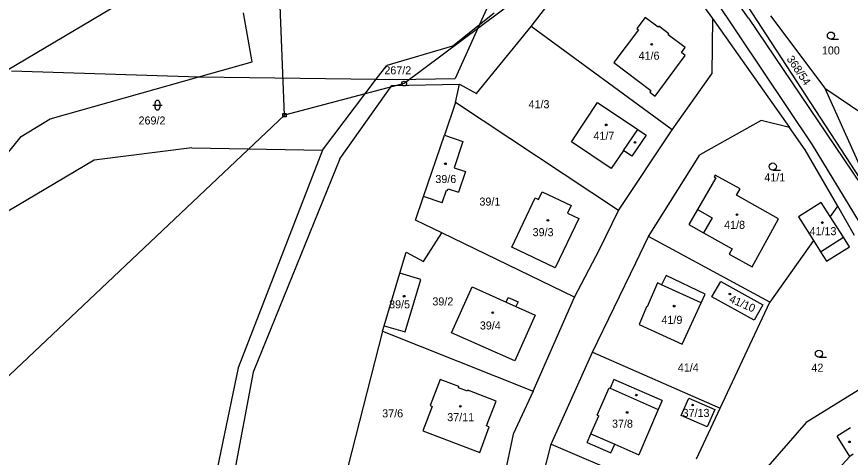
# Model space of a CAD drawing. Extents: x -762263 to -760336, y -1154405 to -1152076.
# Drawn here: x -761872.6 to -761696.3, y -1152343.6 to -1152250.4 of the extents above; entities that cross this region are included whole.
import ezdxf

# ---------------------------------------------------------------- set-up
doc = ezdxf.new("R2010")
doc.units = 0
for name, color, linetype in [('Vrstva 1', 7, 'Continuous'), ('Vrstva 12', 7, 'Continuous'), ('Vrstva 18', 7, 'Continuous'), ('Vrstva 19', 7, 'Continuous'), ('Vrstva 25', 7, 'Continuous'), ('Vrstva 26', 7, 'Continuous'), ('Vrstva 4', 7, 'Continuous'), ('Vrstva 6', 7, 'Continuous')]:
    doc.layers.add(name, color=color, linetype=linetype)

msp = doc.modelspace()

# ---------------------------------------------------------------- linework, layer by layer
at = {"layer": 'Vrstva 1'}
for p, q in [((-761763.84, -1152252.53), (-761746.91, -1152230.45)), ((-761724.89, -1152237.64), (-761678.25, -1152309.43)), ((-761731.11, -1152242.91), (-761725.49, -1152250.86)), ((-761822.85, -1152259.96), (-761824.63, -1152249.61)), ((-761774.74, -1152252.11), (-761771.66, -1152249.65)), ((-761713.2, -1152250.29), (-761701.68, -1152265.53)), ((-761739.7, -1152250.59), (-761741.46, -1152252.93)), ((-761736.99, -1152252.63), (-761739.7, -1152250.59)), ((-761725.49, -1152250.86), (-761725.62, -1152262.52)), ((-761725.49, -1152250.86), (-761709.21, -1152273.89)), ((-761780.45, -1152256.68), (-761774.74, -1152252.11)), ((-761775.35, -1152266.68), (-761763.84, -1152252.53)), ((-761733.96, -1152274.4), (-761763.84, -1152252.53)), ((-761741.1, -1152253.19), (-761746.3, -1152260.1)), ((-761741.46, -1152252.93), (-761741.1, -1152253.19)), ((-761736.85, -1152252.46), (-761736.99, -1152252.63)), ((-761734.69, -1152254.09), (-761736.85, -1152252.46)), ((-761734.81, -1152254.26), (-761734.69, -1152254.09)), ((-761731.26, -1152256.95), (-761734.81, -1152254.26)), ((-761780.45, -1152256.68), (-761794.38, -1152260.75)), ((-761732.04, -1152258.04), (-761731.26, -1152256.95)), ((-761737.56, -1152267.28), (-761731.22, -1152258.65)), ((-761731.22, -1152258.65), (-761732.04, -1152258.04)), ((-761834.11, -1152263.15), (-761822.85, -1152259.96)), ((-761796.57, -1152263.65), (-761794.38, -1152260.75)), ((-761746.3, -1152260.1), (-761738.48, -1152266.03)), ((-761733.96, -1152274.4), (-761725.62, -1152262.52)), ((-761865.57, -1152272.05), (-761834.11, -1152263.15)), ((-761807.94, -1152278.7), (-761796.57, -1152263.65)), ((-761804.26, -1152280.52), (-761793.31, -1152264.99)), ((-761793.31, -1152264.99), (-761778.95, -1152264.69)), ((-761779.84, -1152268.59), (-761778.95, -1152264.69)), ((-761778.95, -1152264.69), (-761775.35, -1152266.68)), ((-761738.48, -1152266.03), (-761738.74, -1152266.38)), ((-761701.68, -1152265.53), (-761693.47, -1152271.1)), ((-761701.68, -1152265.53), (-761694.17, -1152282.36)), ((-761738.74, -1152266.38), (-761737.56, -1152267.28)), ((-761779.84, -1152268.59), (-761782.18, -1152275.5)), ((-761745.34, -1152291.41), (-761779.84, -1152268.59)), ((-761755.32, -1152276.89), (-761749.78, -1152268.59)), ((-761749.78, -1152268.59), (-761741.27, -1152274.29)), ((-761871.68, -1152275.77), (-761865.57, -1152272.05)), ((-761715.15, -1152272.38), (-761728.14, -1152279.66)), ((-761709.21, -1152273.89), (-761715.15, -1152272.38)), ((-761745.34, -1152291.41), (-761733.96, -1152274.4)), ((-761741.27, -1152274.29), (-761739.52, -1152275.47)), ((-761705.86, -1152278.63), (-761709.21, -1152273.89)), ((-761888.89, -1152296.93), (-761871.68, -1152275.77)), ((-761786.59, -1152288.5), (-761782.18, -1152275.5)), ((-761782.18, -1152275.5), (-761778.24, -1152276.84)), ((-761739.52, -1152275.47), (-761742.5, -1152279.97)), ((-761835.61, -1152278.2), (-761856.23, -1152280.8)), ((-761835.61, -1152278.2), (-761807.94, -1152278.7)), ((-761778.24, -1152276.84), (-761780.11, -1152282.38)), ((-761746.88, -1152282.56), (-761755.32, -1152276.89)), ((-761807.94, -1152278.7), (-761825.79, -1152324.72)), ((-761744.29, -1152278.77), (-761746.88, -1152282.56)), ((-761742.5, -1152279.97), (-761744.29, -1152278.77)), ((-761739.03, -1152296.9), (-761728.14, -1152279.66)), ((-761698.99, -1152290.5), (-761705.86, -1152278.63)), ((-761856.23, -1152280.8), (-761887.2, -1152299.09)), ((-761804.26, -1152280.52), (-761822.59, -1152325.61)), ((-761780.11, -1152282.38), (-761777.74, -1152283.19)), ((-761777.74, -1152283.19), (-761779.22, -1152287.55)), ((-761724.73, -1152284.55), (-761728.62, -1152291.21)), ((-761724.9, -1152283.94), (-761725.13, -1152284.33)), ((-761725.13, -1152284.33), (-761724.73, -1152284.55)), ((-761719.64, -1152286.87), (-761724.9, -1152283.94)), ((-761782.66, -1152289.83), (-761781.7, -1152287.16)), ((-761781.7, -1152287.16), (-761781.5, -1152287.22)), ((-761781.5, -1152287.22), (-761781.37, -1152286.83)), ((-761781.37, -1152286.83), (-761779.22, -1152287.55)), ((-761720.38, -1152288.19), (-761719.64, -1152286.87)), ((-761788.28, -1152293.48), (-761786.59, -1152288.5)), ((-761782.66, -1152289.83), (-761786.59, -1152288.5)), ((-761767.92, -1152299.16), (-761762.95, -1152288.76)), ((-761762.95, -1152288.76), (-761762.26, -1152289.08)), ((-761762.26, -1152289.08), (-761761.49, -1152287.46)), ((-761761.49, -1152287.46), (-761755.35, -1152290.38)), ((-761711.48, -1152293.18), (-761720.38, -1152288.19)), ((-761755.35, -1152290.38), (-761756.13, -1152292.01)), ((-761702.46, -1152289.73), (-761707.29, -1152292.79)), ((-761700.56, -1152292.72), (-761702.46, -1152289.73)), ((-761699.17, -1152290.75), (-761700.56, -1152292.72)), ((-761698.99, -1152290.5), (-761699.17, -1152290.75)), ((-761695.4, -1152296.7), (-761698.99, -1152290.5)), ((-761756.13, -1152292.01), (-761753.77, -1152293.14)), ((-761749.33, -1152299.67), (-761745.34, -1152291.41)), ((-761728.62, -1152291.21), (-761730.46, -1152294.36)), ((-761782.73, -1152296.16), (-761788.28, -1152293.48)), ((-761753.77, -1152293.14), (-761758.71, -1152303.56)), ((-761730.46, -1152294.36), (-761727.39, -1152296.16)), ((-761717.08, -1152303.34), (-761711.48, -1152293.18)), ((-761707.29, -1152292.79), (-761704.13, -1152297.78)), ((-761697.79, -1152297.1), (-761700.56, -1152292.72)), ((-761786.6, -1152302.23), (-761782.73, -1152296.16)), ((-761754.68, -1152309.73), (-761782.73, -1152296.16)), ((-761741.68, -1152302.49), (-761739.03, -1152296.9)), ((-761713.32, -1152310.79), (-761739.03, -1152296.9)), ((-761727.39, -1152296.16), (-761721.32, -1152299.52)), ((-761704.13, -1152297.78), (-761713.32, -1152310.79)), ((-761704.13, -1152297.78), (-761702.62, -1152300.16)), ((-761696.52, -1152299.1), (-761697.79, -1152297.1)), ((-761758.71, -1152303.56), (-761767.92, -1152299.16)), ((-761721.32, -1152299.52), (-761721.94, -1152300.65)), ((-761701.38, -1152302.12), (-761696.52, -1152299.1)), ((-761791.58, -1152304.71), (-761790.28, -1152300.21)), ((-761790.28, -1152300.21), (-761786.6, -1152302.23)), ((-761754.68, -1152309.73), (-761749.33, -1152299.67)), ((-761721.94, -1152300.65), (-761717.08, -1152303.34)), ((-761702.62, -1152300.16), (-761701.38, -1152302.12)), ((-761750.83, -1152321.42), (-761741.68, -1152302.49)), ((-761794.88, -1152315.8), (-761791.58, -1152304.71)), ((-761787.13, -1152306), (-761791.58, -1152304.71)), ((-761790.45, -1152317.12), (-761787.13, -1152306)), ((-761735.25, -1152305.18), (-761736.27, -1152307.12)), ((-761727.04, -1152309.13), (-761735.25, -1152305.18)), ((-761725.59, -1152309.69), (-761723.7, -1152306.45)), ((-761723.7, -1152306.45), (-761714.85, -1152311.4)), ((-761780.69, -1152317.27), (-761776.31, -1152307.56)), ((-761776.31, -1152307.56), (-761769.1, -1152310.81)), ((-761737.13, -1152306.73), (-761739.29, -1152311.83)), ((-761736.27, -1152307.12), (-761737.13, -1152306.73)), ((-761769.1, -1152310.81), (-761768.65, -1152309.8)), ((-761768.65, -1152309.8), (-761766.58, -1152310.73)), ((-761763.36, -1152329.65), (-761754.68, -1152309.73)), ((-761727.87, -1152310.95), (-761727.04, -1152309.13)), ((-761716.64, -1152314.6), (-761725.59, -1152309.69)), ((-761766.58, -1152310.73), (-761767.04, -1152311.74)), ((-761767.04, -1152311.74), (-761762.96, -1152313.58)), ((-761739.43, -1152311.77), (-761740.99, -1152315.55)), ((-761739.29, -1152311.83), (-761739.43, -1152311.77)), ((-761731.86, -1152319.71), (-761727.87, -1152310.95)), ((-761723.87, -1152333.22), (-761713.32, -1152310.79)), ((-761714.85, -1152311.4), (-761716.64, -1152314.6)), ((-761762.96, -1152313.58), (-761767.27, -1152323.22)), ((-761795.26, -1152316.98), (-761802.58, -1152345.63)), ((-761795.26, -1152316.98), (-761794.88, -1152315.8)), ((-761795.26, -1152316.98), (-761763.36, -1152329.65)), ((-761794.88, -1152315.8), (-761790.45, -1152317.12)), ((-761767.27, -1152323.22), (-761780.69, -1152317.27)), ((-761740.99, -1152315.55), (-761731.86, -1152319.71)), ((-761759.59, -1152340.87), (-761750.83, -1152321.42)), ((-761750.83, -1152321.42), (-761723.87, -1152333.22)), ((-761681.01, -1152320.98), (-761705.66, -1152336.28)), ((-761825.79, -1152324.72), (-761830.82, -1152348.81)), ((-761822.59, -1152325.61), (-761827.15, -1152349.83)), ((-761783.06, -1152327.15), (-761785.2, -1152332.69)), ((-761779.11, -1152328.67), (-761783.06, -1152327.15)), ((-761746.3, -1152327.18), (-761747.12, -1152329.02)), ((-761736.13, -1152331.62), (-761746.3, -1152327.18)), ((-761779.2, -1152328.91), (-761779.11, -1152328.67)), ((-761777.29, -1152329.64), (-761779.2, -1152328.91)), ((-761777.2, -1152329.41), (-761777.29, -1152329.64)), ((-761771.21, -1152331.72), (-761777.2, -1152329.41)), ((-761749.85, -1152334.73), (-761747.3, -1152328.96)), ((-761747.3, -1152328.96), (-761747.12, -1152329.02)), ((-761763.36, -1152329.65), (-761767.6, -1152338.7)), ((-761732.11, -1152334.8), (-761730.5, -1152331.13)), ((-761730.5, -1152331.13), (-761724.98, -1152333.52)), ((-761784.74, -1152332.87), (-761786.72, -1152337.99)), ((-761785.2, -1152332.69), (-761784.74, -1152332.87)), ((-761773.23, -1152336.95), (-761771.21, -1152331.72)), ((-761736.13, -1152331.62), (-761736.93, -1152333.49)), ((-761751.17, -1152338.65), (-761749.51, -1152334.87)), ((-761749.85, -1152334.73), (-761749.51, -1152334.87)), ((-761736.93, -1152333.49), (-761741.03, -1152343.09)), ((-761726.58, -1152337.18), (-761732.11, -1152334.8)), ((-761728.86, -1152343.91), (-761723.87, -1152333.22)), ((-761724.98, -1152333.52), (-761726.58, -1152337.18)), ((-761705.66, -1152336.28), (-761722.74, -1152355.74)), ((-761786.72, -1152337.99), (-761774.69, -1152342.59)), ((-761774.69, -1152342.59), (-761772.67, -1152337.16)), ((-761772.67, -1152337.16), (-761773.23, -1152336.95)), ((-761696.26, -1152337.36), (-761699.1, -1152339.15)), ((-761767.6, -1152338.7), (-761770.81, -1152353.77)), ((-761751.97, -1152340.46), (-761751.17, -1152338.65)), ((-761696.41, -1152343.42), (-761699.1, -1152339.15)), ((-761767.56, -1152371.68), (-761759.59, -1152340.87)), ((-761759.59, -1152340.87), (-761732.75, -1152352.26)), ((-761751.97, -1152340.46), (-761746.94, -1152342.67)), ((-761746.94, -1152342.67), (-761746.15, -1152340.85)), ((-761746.15, -1152340.85), (-761741.03, -1152343.09)), ((-761703.88, -1152351.54), (-761696.41, -1152343.42))]:
    msp.add_line(p, q, dxfattribs=at)
at = {"layer": 'Vrstva 12'}
for p, q in [((-761816, -1152271.28), (-761819.69, -1152174.42)), ((-761774.59, -1152202.51), (-761992.86, -1152331.75)), ((-761756.68, -1152239.19), (-761790.68, -1152264.59)), ((-761790.68, -1152264.59), (-761816, -1152271.28)), ((-761816, -1152271.28), (-761894.4, -1152345.35))]:
    msp.add_line(p, q, dxfattribs=at)
at = {"layer": 'Vrstva 25'}
for p, q in [((-761700.42, -1152255.19), (-761698.82, -1152255.19)), ((-761843.86, -1152269.15), (-761841.86, -1152269.15)), ((-761843.36, -1152269.65), (-761843.36, -1152268.65)), ((-761842.36, -1152268.65), (-761842.36, -1152269.65)), ((-761712.71, -1152282.88), (-761711.11, -1152282.88)), ((-761702.96, -1152322.45), (-761701.36, -1152322.45))]:
    msp.add_line(p, q, dxfattribs=at)
for centre, radius in [((-761700.42, -1152254.44), 0.75), ((-761738.33, -1152256.28), 0.175), ((-761747.94, -1152273.32), 0.175), ((-761741.84, -1152277.04), 0.175), ((-761781.94, -1152281.55), 0.175), ((-761712.71, -1152282.13), 0.75), ((-761720.27, -1152292.3), 0.175), ((-761760.28, -1152293.5), 0.175), ((-761702.22, -1152293.98), 0.175), ((-761790.69, -1152309.55), 0.175), ((-761721.78, -1152309.09), 0.175), ((-761733.57, -1152311.65), 0.175), ((-761771.96, -1152313.05), 0.175), ((-761702.96, -1152321.7), 0.75), ((-761741.58, -1152330.47), 0.175), ((-761778.81, -1152332.83), 0.175), ((-761729.66, -1152332.57), 0.175), ((-761743.53, -1152334.13), 0.175), ((-761696.49, -1152340.35), 0.175)]:
    msp.add_circle(centre, radius, dxfattribs=at)
for centre, start, end in [((-761842.86, -1152268.65), 0, 180), ((-761842.86, -1152269.65), 180, 0)]:
    msp.add_arc(centre, 0.5, start, end, dxfattribs=at)
at = {"layer": 'Vrstva 26'}
msp.add_lwpolyline([(-761816.335, -1152270.945), (-761815.665, -1152270.945), (-761815.665, -1152271.615), (-761816.335, -1152271.615)], close=True, dxfattribs=at)
msp.add_circle((-761790.68, -1152264.59), 0.5, dxfattribs=at)
at = {"layer": 'Vrstva 4'}
for p, q in [((-761704.32, -1152277.54), (-761728.12, -1152241.96)), ((-761717.85, -1152250.76), (-761721.96, -1152244.9)), ((-761717.85, -1152250.76), (-761678.25, -1152309.43)), ((-761744.29, -1152278.77), (-761741.27, -1152274.29)), ((-761676.88, -1152322.72), (-761704.32, -1152277.54)), ((-761728.62, -1152291.21), (-761725.55, -1152293.01)), ((-761725.55, -1152293.01), (-761727.39, -1152296.16)), ((-761702.62, -1152300.16), (-761697.79, -1152297.1)), ((-761727.87, -1152310.95), (-761736.27, -1152307.12)), ((-761769.1, -1152310.81), (-761767.04, -1152311.74)), ((-761747.12, -1152329.02), (-761736.93, -1152333.49)), ((-761751.17, -1152338.65), (-761746.15, -1152340.85)), ((-761695.69, -1152342.97), (-761696.41, -1152343.42))]:
    msp.add_line(p, q, dxfattribs=at)
at = {"layer": 'Vrstva 6'}
for p, q in [((-761760.08, -1152219.55), (-761774.74, -1152252.11)), ((-761774.74, -1152252.11), (-761779.88, -1152263.54)), ((-761873.76, -1152261.91), (-761834.11, -1152263.15)), ((-761834.11, -1152263.15), (-761796.57, -1152263.65)), ((-761796.57, -1152263.65), (-761792.36, -1152263.71)), ((-761792.36, -1152263.71), (-761779.88, -1152263.54))]:
    msp.add_line(p, q, dxfattribs=at)

# ---------------------------------------------------------------- texts
at = {"layer": 'Vrstva 18'}
for s, p in [('100', (-761702.33, -1152258.43)), ('267/2', (-761794.87, -1152262.64)), ('41/3', (-761764.373, -1152269.8)), ('269/2', (-761846.86, -1152273.24)), ('41/1', (-761714.508, -1152285.27)), ('39/1', (-761774.763, -1152290.39)), ('39/2', (-761784.713, -1152311.5)), ('41/4', (-761732.796, -1152325.48)), ('42', (-761704.539, -1152325.52)), ('37/6', (-761795.323, -1152335.18))]:
    msp.add_text(s, height=1.7, dxfattribs=at).set_placement(p)
msp.add_text('368/54', height=1.7, rotation=304.24059, dxfattribs=at).set_placement((-761709.87, -1152259.389))
at = {"layer": 'Vrstva 19'}
for s, p in [('41/6', (-761741.096, -1152259.54)), ('41/7', (-761750.646, -1152276.48)), ('39/6', (-761784.083, -1152285.62)), ('41/8', (-761723.006, -1152295.31)), ('39/3', (-761763.508, -1152296.86)), ('41/13', (-761704.944, -1152296.65)), ('39/5', (-761793.868, -1152312.12)), ('41/9', (-761736.256, -1152315.4)), ('39/4', (-761774.673, -1152316.59)), ('37/11', (-761781.573, -1152335.98)), ('37/13', (-761731.789, -1152335.08)), ('37/8', (-761746.721, -1152337.36))]:
    msp.add_text(s, height=1.7, dxfattribs=at).set_placement(p)
msp.add_text('41/10', height=1.7, rotation=336.49811, dxfattribs=at).set_placement((-761722.085, -1152310.748))

doc.saveas('drawing.dxf')
